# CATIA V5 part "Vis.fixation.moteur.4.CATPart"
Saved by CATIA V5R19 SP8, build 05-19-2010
Part number: Vis.fixation.moteur.4
Bounding box of the stored display mesh (mm): x -5.5 to 17.5, y -17 to -11, z -20.5 to 2.5
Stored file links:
  G:\EU_thinkMotion\CFAO_2010\MMS_groupe3\MMS_groupe3\jbonnamy\jbonnamy_cfao\Vis.fixation.moteur.4.CATPart
  C:\Users\Micheline\Desktop\projet CFAO\Nouveau dossier\temp\Nouveau dossier\Vis.fixation.CATPart
  G:\EU_thinkMotion\CFAO_2010\MMS_groupe3\MMS_groupe3\jbonnamy\jbonnamy_cfao\jbonnamy_suspension.arriere.directionnelle.CATProduct
  G:\EU_thinkMotion\CFAO_2010\MMS_groupe3\MMS_groupe3\jbonnamy\jbonnamy_cfao\Vis.fixation.moteur.3.CATPart
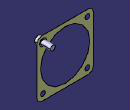
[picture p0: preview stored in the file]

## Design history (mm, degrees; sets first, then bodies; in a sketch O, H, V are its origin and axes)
External parameters (linked from other documents)
  External.Epaisseur.support.10 = 1.5 mm
  External.Diametre.vis.fixation = 2 mm
Set1
  DatumSurface1: linked copy from another document
Body1 (main body)
  Sketch1 on DatumSurface1, origin (15, -15, 0), H (1, 0, 0), V (0, 0, 1)
    circle A1 centre (0, 0) radius 1
    radius A1 = 1 {= External.Diametre.vis.fixation /2}
  Pad1: profile Sketch1, direction (0, 1, 0), length 4 {= 2*External.Epaisseur.support.10 +1mm}
  Sketch2 on DatumSurface1, origin (15, -15, 0), H (1, 0, 0), V (0, 0, 1)
    circle A1 centre (0, 0) radius 1.5
    radius A1 = 1.5 {= 3*External.Diametre.vis.fixation /4}
  Pad2: profile Sketch2, direction (0, -1, 0), length 2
